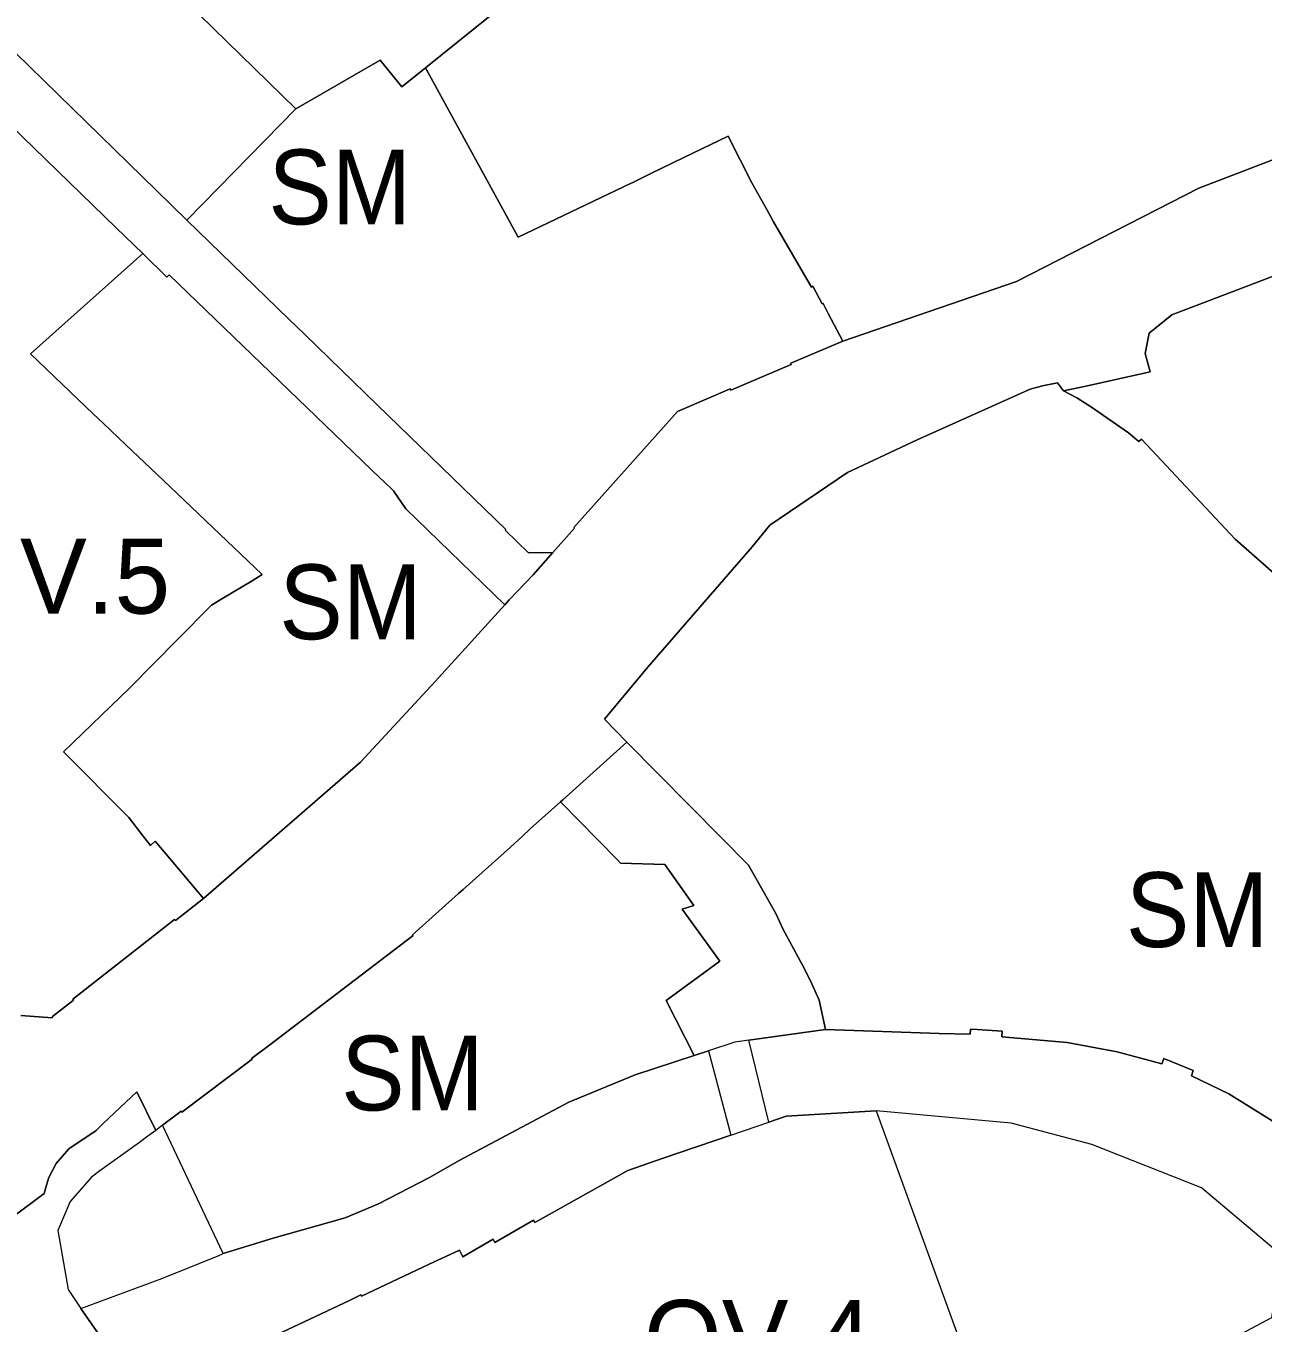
# Model space of a CAD drawing. Extents: x -650451 to -642268, y -1075216 to -1066610.
# Drawn here: x -647355.8 to -647157.3, y -1070317.4 to -1070109.3 of the extents above; entities that cross this region are included whole.
import ezdxf

# ---------------------------------------------------------------- set-up
doc = ezdxf.new("R2010")
doc.units = 0
doc.header["$LTSCALE"] = 4.8
for name, color, linetype, lineweight in [('11', 7, 'Continuous', 13), ('15', 7, 'Continuous', 13), ('18', 7, 'Continuous', 13), ('24', 7, 'Continuous', 13), ('45', 7, 'Continuous', 13), ('9', 7, 'Continuous', 13)]:
    doc.layers.add(name, color=color, linetype=linetype, lineweight=lineweight)
doc.layers.add('62', color=7, linetype='Continuous')

msp = doc.modelspace()

# ---------------------------------------------------------------- linework, layer by layer
at = {"layer": '11'}
for points in [[(-647291.67, -1070116.04), (-647278.81, -1070105.73), (-647258.36, -1070096.89), (-647230.37, -1070074.09), (-647238.99, -1070059.05), (-647195.933, -1070040.107)], [(-647094.36, -1070102.91), (-647093.03, -1070110.71), (-647109.06, -1070114.67), (-647134.29, -1070122.54), (-647167.62, -1070135.33), (-647196.84, -1070150.3), (-647219.58, -1070158.11), (-647224.72, -1070159.87)], [(-647224.72, -1070159.87), (-647227.04, -1070155.44), (-647227.88, -1070153.85), (-647228.02, -1070153.9), (-647229.53, -1070151.08), (-647229.75, -1070151.22), (-647235.82, -1070140.75), (-647236.92, -1070138.78), (-647239.33, -1070134.48), (-647243.13, -1070126.97), (-647250.23, -1070130.43), (-647255.52, -1070133), (-647258.53, -1070134.47), (-647258.67, -1070134.54), (-647276.77, -1070143.22), (-647291.67, -1070116.04)], [(-647434.91, -1070183.16), (-647412.16, -1070162.89), (-647367.48, -1070123.07), (-647363.9, -1070119.75), (-647341.29, -1070141.7), (-647337.02, -1070145.84)], [(-647337.02, -1070145.84), (-647355.06, -1070161.92), (-647344.91, -1070171.59), (-647343.38, -1070173.05), (-647339.69, -1070176.56), (-647333.74, -1070182.2), (-647317.85, -1070197.29), (-647319.45, -1070198.33), (-647324.35, -1070201.23), (-647326.02, -1070202.22), (-647331.39, -1070207.67), (-647339.1, -1070215.49), (-647349.72, -1070225.74), (-647339.28, -1070236.31), (-647336.97, -1070239.27), (-647335.77, -1070240.77), (-647335.01, -1070240.09), (-647327.26, -1070249.3)], [(-647327.26, -1070249.3), (-647331.78, -1070252.83), (-647331.91, -1070252.67), (-647348.25, -1070265.44), (-647348.13, -1070265.59), (-647351.52, -1070268.23), (-647351.56, -1070268.45), (-647356.58, -1070268.06)], [(-647236.567, -1070285.154), (-647233.82, -1070284.22), (-647232.87, -1070284.15), (-647219.36, -1070283.36), (-647199.79, -1070337.21)], [(-647336.3, -1070330.36), (-647325.69, -1070324.05), (-647303.74, -1070313.73), (-647302.03, -1070312.86), (-647301.91, -1070313.05), (-647291.17, -1070307.98), (-647286.23, -1070305.72), (-647285.69, -1070306.76), (-647280.83, -1070303.93), (-647280.52, -1070304.49), (-647274.32, -1070300.9), (-647274.12, -1070301.25), (-647263.72, -1070295.43), (-647259.22, -1070292.91), (-647253.53, -1070290.92), (-647242.698, -1070287.238), (-647236.567, -1070285.154)]]:
    msp.add_lwpolyline(points, dxfattribs=at)
at = {"layer": '15'}
for points in [[(-647362.87, -1070107.74), (-647359.8, -1070111.34), (-647357.4, -1070113.69), (-647334.81, -1070135.73), (-647329.932, -1070140.465)], [(-647337.02, -1070145.84), (-647341.29, -1070141.7), (-647363.9, -1070119.75), (-647367.48, -1070123.07), (-647412.16, -1070162.89), (-647434.91, -1070183.16)], [(-647329.932, -1070140.465), (-647313.59, -1070156.33), (-647311.04, -1070158.81), (-647299.35, -1070170.16), (-647278.8, -1070190.09), (-647278.9, -1070190.2), (-647275.12, -1070193.84), (-647271.26, -1070193.8)], [(-647189.3, -1070167.85), (-647185.48, -1070167.02), (-647175.42, -1070164.82), (-647176.2, -1070161.88), (-647175.57, -1070158.57), (-647171.94, -1070155.64), (-647153, -1070148.46), (-647136.65, -1070141.75)], [(-647278.96, -1070202.16), (-647294.81, -1070186.79), (-647296.79, -1070183.9), (-647298.41, -1070182.33), (-647298.86, -1070181.89), (-647332.76, -1070149.21), (-647333.14, -1070149.61), (-647337.02, -1070145.84)], [(-647098.01, -1070229.05), (-647111.9, -1070224.83), (-647118.41, -1070220.95), (-647117.77, -1070219.6), (-647127.89, -1070215.01), (-647128.12, -1070215.02), (-647128.24, -1070215.02), (-647133, -1070212.16), (-647133.27, -1070212.02), (-647137.83, -1070209.38), (-647150.22, -1070201.78), (-647161.79, -1070191.62), (-647176.8, -1070175.6), (-647177.2, -1070175.96), (-647178.9, -1070174.56), (-647184.81, -1070170.44), (-647187.19, -1070168.95), (-647189.3, -1070167.85)], [(-647271.26, -1070193.8), (-647274.38, -1070197.37), (-647278.23, -1070201.38), (-647278.96, -1070202.16)], [(-647270.03, -1070233.79), (-647269.65, -1070233.45), (-647259.35, -1070224.18)], [(-647259.35, -1070224.18), (-647244.22, -1070239.51), (-647239.84, -1070243.95), (-647235.44, -1070251.71), (-647234.29, -1070254.23), (-647231.2, -1070260), (-647229.92, -1070262.5), (-647228.49, -1070265.6), (-647227.49, -1070270.31), (-647239.781, -1070272.031)], [(-647248.56, -1070274.48), (-647253.03, -1070265.67), (-647244.42, -1070259.35), (-647250.5, -1070251), (-647248.62, -1070250.39), (-647253.28, -1070243.85), (-647260.36, -1070243.59), (-647260.91, -1070243.03), (-647270.03, -1070233.79)], [(-647239.781, -1070272.031), (-647242.06, -1070272.35), (-647246.28, -1070273.733), (-647248.56, -1070274.48)], [(-647368.29, -1070307.63), (-647367.038, -1070305.027), (-647366.9, -1070305.07), (-647365.59, -1070306.17), (-647368.02, -1070301.95), (-647361.04, -1070301.21), (-647359.59, -1070300.92), (-647358.15, -1070300.54), (-647352.83, -1070296.62), (-647352.48, -1070295.25), (-647352.07, -1070294.06), (-647350.9, -1070291.81), (-647348.88, -1070289.42), (-647344.5, -1070286.5), (-647343.35, -1070285.4), (-647337.99, -1070280.29), (-647334.91, -1070286.51)], [(-647334.91, -1070286.51), (-647336.22, -1070287.43), (-647337.56, -1070288.43), (-647343.9, -1070292.96), (-647345.27, -1070293.99), (-647348.677, -1070297.894), (-647350.67, -1070302.55), (-647349, -1070312), (-647346.97, -1070315.05), (-647336.3, -1070330.36)]]:
    msp.add_lwpolyline(points, dxfattribs=at)
at = {"layer": '18'}
msp.add_line((-647329.932, -1070140.465), (-647312.485, -1070122.583), dxfattribs=at)
for points in [[(-647312.485, -1070122.583), (-647298.91, -1070114.8), (-647295.47, -1070119.09), (-647291.67, -1070116.04)], [(-647291.67, -1070116.04), (-647276.77, -1070143.22), (-647258.67, -1070134.54), (-647258.53, -1070134.47), (-647255.52, -1070133), (-647250.23, -1070130.43), (-647243.13, -1070126.97), (-647239.33, -1070134.48), (-647236.92, -1070138.78), (-647235.82, -1070140.75), (-647229.75, -1070151.22), (-647229.53, -1070151.08), (-647228.02, -1070153.9), (-647227.88, -1070153.85), (-647227.04, -1070155.44), (-647224.72, -1070159.87)], [(-647271.26, -1070193.8), (-647275.12, -1070193.84), (-647278.9, -1070190.2), (-647278.8, -1070190.09), (-647299.35, -1070170.16), (-647311.04, -1070158.81), (-647313.59, -1070156.33), (-647329.932, -1070140.465)], [(-647327.26, -1070249.3), (-647335.01, -1070240.09), (-647335.77, -1070240.77), (-647336.97, -1070239.27), (-647339.28, -1070236.31), (-647349.72, -1070225.74), (-647339.1, -1070215.49), (-647331.39, -1070207.67), (-647326.02, -1070202.22), (-647324.35, -1070201.23), (-647319.45, -1070198.33), (-647317.85, -1070197.29), (-647333.74, -1070182.2), (-647339.69, -1070176.56), (-647343.38, -1070173.05), (-647344.91, -1070171.59), (-647355.06, -1070161.92), (-647337.02, -1070145.84)], [(-647337.02, -1070145.84), (-647333.14, -1070149.61), (-647332.76, -1070149.21), (-647298.86, -1070181.89), (-647298.41, -1070182.33), (-647296.79, -1070183.9), (-647294.81, -1070186.79), (-647278.96, -1070202.16)], [(-647224.72, -1070159.87), (-647233.07, -1070163.43), (-647232.99, -1070163.62), (-647242.69, -1070167.74), (-647242.77, -1070167.55), (-647251.26, -1070171.18), (-647257.97, -1070178.72), (-647267.88, -1070189.78), (-647267.77, -1070189.88), (-647271.26, -1070193.8)], [(-647259.35, -1070224.18), (-647262.94, -1070220.53), (-647256.07, -1070212.25), (-647239.24, -1070192.85), (-647236.4, -1070189.4), (-647223.97, -1070180.95), (-647212.77, -1070175.69), (-647194.68, -1070167.58), (-647192.66, -1070167.03), (-647190.29, -1070166.55), (-647189.3, -1070167.85)], [(-647189.3, -1070167.85), (-647187.19, -1070168.95), (-647184.81, -1070170.44), (-647178.9, -1070174.56), (-647177.2, -1070175.96), (-647176.8, -1070175.6), (-647161.79, -1070191.62), (-647150.22, -1070201.78), (-647137.83, -1070209.38), (-647133.27, -1070212.02), (-647133, -1070212.16), (-647128.24, -1070215.02), (-647128.12, -1070215.02), (-647127.89, -1070215.01), (-647117.77, -1070219.6), (-647118.41, -1070220.95), (-647111.9, -1070224.83), (-647098.01, -1070229.05)], [(-647278.96, -1070202.16), (-647290.12, -1070214.47), (-647302.11, -1070227.4), (-647327.26, -1070249.3)], [(-647227.49, -1070270.31), (-647228.49, -1070265.6), (-647229.92, -1070262.5), (-647231.2, -1070260), (-647234.29, -1070254.23), (-647235.44, -1070251.71), (-647239.84, -1070243.95), (-647244.22, -1070239.51), (-647259.35, -1070224.18)], [(-647333.87, -1070285.66), (-647330.88, -1070283.41), (-647330.78, -1070283.55), (-647319.49, -1070275.08), (-647319.59, -1070274.94), (-647316.66, -1070272.74), (-647293.66, -1070255.2), (-647293.74, -1070255.11), (-647286.37, -1070248.5), (-647285.62, -1070247.84), (-647278, -1070241.03), (-647276.17, -1070239.32), (-647274.88, -1070238.11), (-647270.03, -1070233.79)], [(-647270.03, -1070233.79), (-647260.91, -1070243.03), (-647260.36, -1070243.59), (-647253.28, -1070243.85), (-647248.62, -1070250.39), (-647250.5, -1070251), (-647244.42, -1070259.35), (-647253.03, -1070265.67), (-647248.56, -1070274.48)], [(-647149.71, -1070288.72), (-647162.8, -1070280.61), (-647168.79, -1070277.75), (-647168.5, -1070276.87), (-647173.22, -1070274.93), (-647173.54, -1070275.79), (-647180.68, -1070273.87), (-647188.74, -1070272.36), (-647199.19, -1070271.47), (-647199.14, -1070270.57), (-647203.16, -1070270.29), (-647204.22, -1070270.22), (-647204.27, -1070271.05), (-647209.25, -1070270.93), (-647227.49, -1070270.31)], [(-647248.56, -1070274.48), (-647258, -1070277.57), (-647268.68, -1070281.94), (-647286.27, -1070291.31), (-647291.02, -1070294.03), (-647299.21, -1070298.24), (-647304.56, -1070300.5), (-647316.11, -1070303.79), (-647324.11, -1070306.21), (-647333.87, -1070285.66)]]:
    msp.add_lwpolyline(points, dxfattribs=at)
at = {"layer": '24'}
for points in [[(-647224.72, -1070159.87), (-647219.58, -1070158.11), (-647196.84, -1070150.3), (-647167.62, -1070135.33), (-647134.29, -1070122.54), (-647109.06, -1070114.67), (-647093.03, -1070110.71), (-647094.36, -1070102.91)], [(-647136.65, -1070141.75), (-647153, -1070148.46), (-647171.94, -1070155.64), (-647175.57, -1070158.57), (-647176.2, -1070161.88), (-647175.42, -1070164.82), (-647185.48, -1070167.02), (-647189.3, -1070167.85)], [(-647271.26, -1070193.8), (-647267.77, -1070189.88), (-647267.88, -1070189.78), (-647257.97, -1070178.72), (-647251.26, -1070171.18), (-647242.77, -1070167.55), (-647242.69, -1070167.74), (-647232.99, -1070163.62), (-647233.07, -1070163.43), (-647224.72, -1070159.87)], [(-647189.3, -1070167.85), (-647190.29, -1070166.55), (-647192.66, -1070167.03), (-647194.68, -1070167.58), (-647212.77, -1070175.69), (-647223.97, -1070180.95), (-647236.4, -1070189.4), (-647239.24, -1070192.85), (-647256.07, -1070212.25), (-647262.94, -1070220.53), (-647259.35, -1070224.18)], [(-647278.96, -1070202.16), (-647278.23, -1070201.38), (-647274.38, -1070197.37), (-647271.26, -1070193.8)], [(-647327.26, -1070249.3), (-647302.11, -1070227.4), (-647290.12, -1070214.47), (-647278.96, -1070202.16)], [(-647259.35, -1070224.18), (-647269.65, -1070233.45), (-647270.03, -1070233.79)], [(-647270.03, -1070233.79), (-647274.88, -1070238.11), (-647276.17, -1070239.32), (-647278, -1070241.03), (-647285.62, -1070247.84), (-647286.37, -1070248.5), (-647293.74, -1070255.11), (-647293.66, -1070255.2), (-647316.66, -1070272.74), (-647319.59, -1070274.94), (-647319.49, -1070275.08), (-647330.78, -1070283.55), (-647330.88, -1070283.41), (-647333.87, -1070285.66), (-647334.91, -1070286.51)], [(-647356.58, -1070268.06), (-647351.56, -1070268.45), (-647351.52, -1070268.23), (-647348.13, -1070265.59), (-647348.25, -1070265.44), (-647331.91, -1070252.67), (-647331.78, -1070252.83), (-647327.26, -1070249.3)], [(-647334.91, -1070286.51), (-647337.99, -1070280.29), (-647343.35, -1070285.4), (-647344.5, -1070286.5), (-647348.88, -1070289.42), (-647350.9, -1070291.81), (-647352.07, -1070294.06), (-647352.48, -1070295.25), (-647352.83, -1070296.62), (-647358.15, -1070300.54), (-647359.59, -1070300.92), (-647361.04, -1070301.21), (-647368.02, -1070301.95), (-647365.59, -1070306.17), (-647366.9, -1070305.07), (-647367.038, -1070305.027), (-647368.29, -1070307.63)]]:
    msp.add_lwpolyline(points, dxfattribs=at)
at = {"layer": '45'}
msp.add_line((-647239.781, -1070272.031), (-647227.49, -1070270.31), dxfattribs=at)
for points in [[(-647227.49, -1070270.31), (-647209.25, -1070270.93), (-647204.27, -1070271.05), (-647204.22, -1070270.22), (-647203.16, -1070270.29), (-647199.14, -1070270.57), (-647199.19, -1070271.47), (-647188.74, -1070272.36), (-647180.68, -1070273.87), (-647173.54, -1070275.79), (-647173.22, -1070274.93), (-647168.5, -1070276.87), (-647168.79, -1070277.75), (-647162.8, -1070280.61), (-647149.71, -1070288.72)], [(-647324.11, -1070306.21), (-647316.11, -1070303.79), (-647304.56, -1070300.5), (-647299.21, -1070298.24), (-647291.02, -1070294.03), (-647286.27, -1070291.31), (-647268.68, -1070281.94), (-647258, -1070277.57), (-647248.56, -1070274.48), (-647246.28, -1070273.733), (-647242.698, -1070287.238)], [(-647219.36, -1070283.36), (-647232.87, -1070284.15), (-647233.82, -1070284.22), (-647236.567, -1070285.154), (-647239.781, -1070272.031)], [(-647199.79, -1070337.21), (-647189.63, -1070330.53), (-647167.43, -1070322.66), (-647155.89, -1070316.51), (-647154.23, -1070306.63), (-647167.15, -1070295.69), (-647184.77, -1070288.73), (-647197.68, -1070285.3), (-647219.36, -1070283.36)], [(-647242.698, -1070287.238), (-647253.53, -1070290.92), (-647259.22, -1070292.91), (-647263.72, -1070295.43), (-647274.12, -1070301.25), (-647274.32, -1070300.9), (-647280.52, -1070304.49), (-647280.83, -1070303.93), (-647285.69, -1070306.76), (-647286.23, -1070305.72), (-647291.17, -1070307.98), (-647301.91, -1070313.05), (-647302.03, -1070312.86), (-647303.74, -1070313.73), (-647325.69, -1070324.05), (-647336.3, -1070330.36), (-647346.97, -1070315.05)], [(-647346.97, -1070315.05), (-647333.97, -1070310.22), (-647324.94, -1070306.63), (-647324.11, -1070306.21)]]:
    msp.add_lwpolyline(points, dxfattribs=at)
at = {"layer": '9'}
for points in [[(-647238.99, -1070059.05), (-647230.37, -1070074.09), (-647258.36, -1070096.89), (-647278.81, -1070105.73), (-647291.67, -1070116.04)], [(-647291.67, -1070116.04), (-647295.47, -1070119.09), (-647298.91, -1070114.8), (-647312.485, -1070122.583), (-647343.454, -1070092.368)]]:
    msp.add_lwpolyline(points, dxfattribs=at)

# ---------------------------------------------------------------- texts
at = {"layer": '62', "width": 0.95}
for p in [(-647316.861, -1070141.138), (-647315.109, -1070207.698), (-647179.297, -1070257.072), (-647305.188, -1070283.28)]:
    msp.add_text('SM', height=12, dxfattribs=at).set_placement(p)
at = {"layer": '62'}
for s, p in [('OV.5', (-647369.192, -1070203.585)), ('OV.4', (-647256.619, -1070325.69))]:
    msp.add_text(s, height=12, dxfattribs=at).set_placement(p)

doc.saveas('drawing.dxf')
